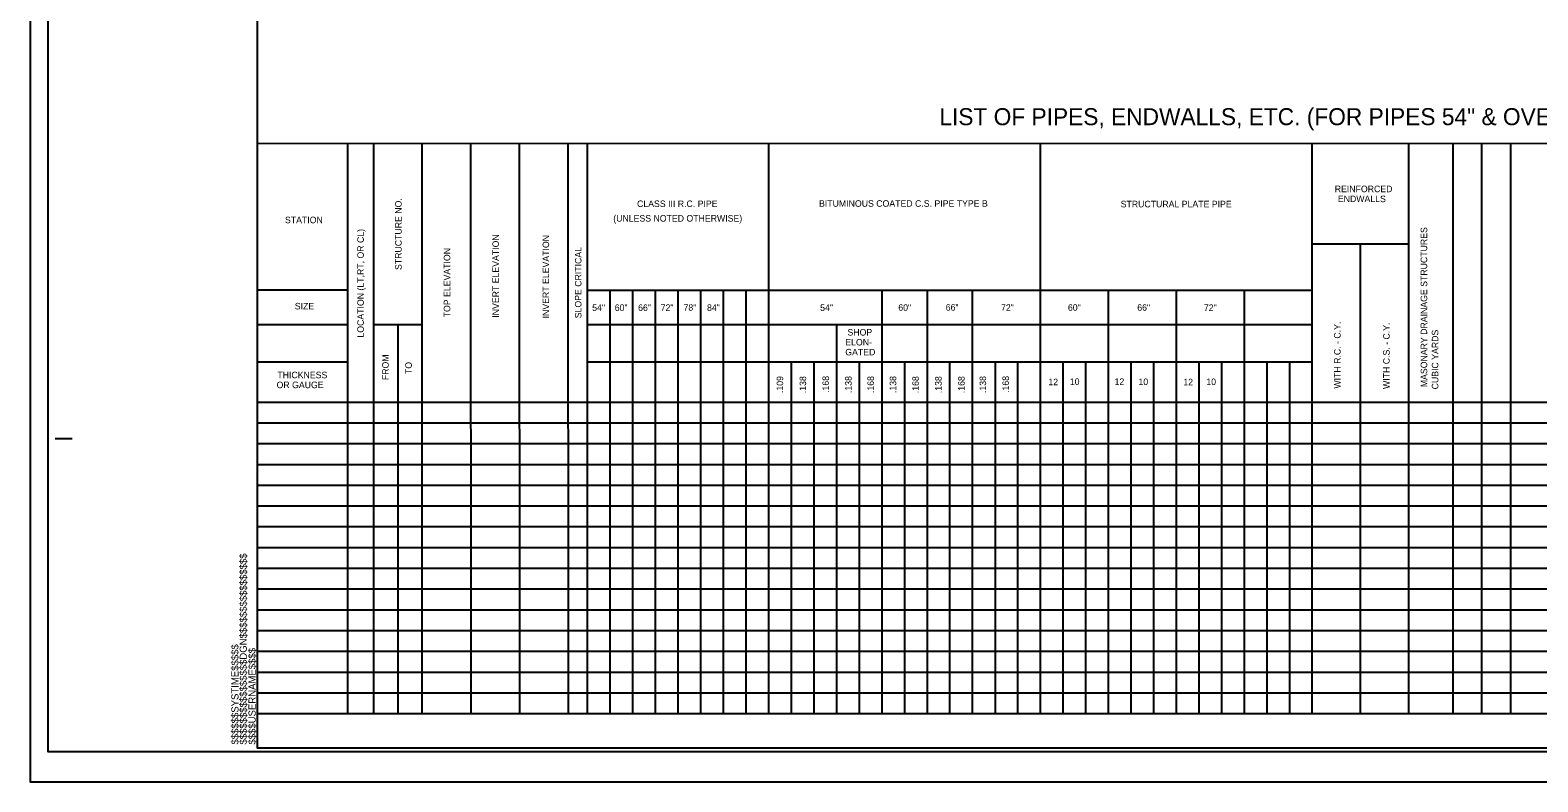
# Model space of a CAD drawing. Extents: x 2530399 to 2530799, y 189629 to 189994.
# Drawn here: x 2530630.3 to 2530741.2, y 189849.1 to 189904.4 of the extents above; entities that cross this region are included whole.
import ezdxf

# ---------------------------------------------------------------- set-up
doc = ezdxf.new("R2010")
doc.units = 0
for name, color, linetype in [('Sheet Plan CELL', 7, 'Continuous'), ('Typical Detail Pavement Repair CELL', 7, 'Continuous'), ('Typical Detail Wedge1 CELL', 7, 'Continuous'), ('Typical Pavement Slope Information CELL', 7, 'Continuous'), ('Typical Shoulder Slope CELL', 7, 'Continuous')]:
    doc.layers.add(name, color=color, linetype=linetype)

msp = doc.modelspace()

# ---------------------------------------------------------------- linework, layer by layer
at = {"layer": 'Sheet Plan CELL'}
for p, q in [((2530630.27, 189959.14), (2530630.27, 189849.14)), ((2530630.27, 189849.14), (2530798.67, 189849.14))]:
    msp.add_line(p, q, dxfattribs=at)
at = {"layer": 'Typical Detail Pavement Repair CELL'}
msp.add_lwpolyline([(2530798.22, 189956.89), (2530631.57, 189956.89), (2530631.57, 189851.38), (2530798.22, 189851.38)], close=True, dxfattribs=at)
at = {"layer": 'Typical Detail Wedge1 CELL'}
msp.add_lwpolyline([(2530798.67, 189959.14), (2530630.27, 189959.14), (2530630.27, 189849.14), (2530798.67, 189849.14)], close=True, dxfattribs=at)
at = {"layer": 'Typical Pavement Slope Information CELL'}
for p, q in [((2530632.12, 189874.39), (2530633.37, 189874.39)), ((2530646.97, 189851.64), (2530646.97, 189851.64))]:
    msp.add_line(p, q, dxfattribs=at)
msp.add_lwpolyline([(2530796.97, 189956.64), (2530646.97, 189956.64), (2530646.97, 189851.64), (2530796.97, 189851.64)], close=True, dxfattribs=at)
at = {"layer": 'Typical Shoulder Slope CELL'}
for p, q in [((2530796.96, 189896.09), (2530646.96, 189896.07)), ((2530653.65, 189854.14), (2530653.65, 189896.06)), ((2530655.56, 189854.14), (2530655.56, 189896.06)), ((2530659.12, 189854.14), (2530659.12, 189896.06)), ((2530662.71, 189854.14), (2530662.7, 189896.06)), ((2530666.29, 189854.14), (2530666.28, 189896.06)), ((2530669.87, 189854.14), (2530669.86, 189896.06)), ((2530671.28, 189854.14), (2530671.28, 189896.07)), ((2530684.62, 189854.14), (2530684.61, 189896.07)), ((2530704.61, 189854.14), (2530704.61, 189896.07)), ((2530724.6, 189854.14), (2530724.6, 189896.07)), ((2530731.71, 189854.14), (2530731.71, 189896.08)), ((2530734.93, 189896.07), (2530734.93, 189854.14)), ((2530737.07, 189854.14), (2530737.07, 189896.07)), ((2530739.21, 189854.14), (2530739.21, 189896.07)), ((2530731.71, 189888.68), (2530724.6, 189888.68)), ((2530728.15, 189854.14), (2530728.15, 189888.68)), ((2530653.65, 189885.29), (2530646.96, 189885.29)), ((2530669.87, 189885.28), (2530669.86, 189885.28)), ((2530671.28, 189885.29), (2530724.6, 189885.29)), ((2530672.95, 189854.14), (2530672.95, 189885.29)), ((2530674.62, 189854.14), (2530674.62, 189885.29)), ((2530676.28, 189854.14), (2530676.28, 189885.29)), ((2530677.95, 189854.14), (2530677.95, 189885.29)), ((2530679.61, 189854.14), (2530679.61, 189885.29)), ((2530681.28, 189854.14), (2530681.28, 189885.29)), ((2530682.95, 189854.14), (2530682.95, 189885.29)), ((2530692.95, 189854.14), (2530692.95, 189885.29)), ((2530696.28, 189854.14), (2530696.28, 189885.29)), ((2530699.61, 189854.14), (2530699.61, 189885.29)), ((2530709.6, 189854.14), (2530709.6, 189885.29)), ((2530714.61, 189854.14), (2530714.61, 189885.29)), ((2530719.6, 189854.14), (2530719.6, 189885.29)), ((2530653.65, 189882.75), (2530646.96, 189882.75)), ((2530659.12, 189882.75), (2530655.56, 189882.75)), ((2530657.34, 189854.14), (2530657.34, 189882.74)), ((2530666.28, 189882.74), (2530666.28, 189882.74)), ((2530669.87, 189882.74), (2530669.86, 189882.74)), ((2530724.6, 189882.75), (2530671.28, 189882.75)), ((2530689.61, 189854.14), (2530689.61, 189882.75)), ((2530653.65, 189880), (2530646.96, 189880)), ((2530724.6, 189880.01), (2530671.28, 189880)), ((2530686.28, 189854.14), (2530686.28, 189880)), ((2530687.94, 189854.14), (2530687.94, 189880)), ((2530691.28, 189854.14), (2530691.28, 189880)), ((2530694.61, 189854.14), (2530694.61, 189880)), ((2530697.94, 189854.14), (2530697.94, 189880)), ((2530701.28, 189854.14), (2530701.28, 189880)), ((2530702.94, 189854.14), (2530702.94, 189880)), ((2530706.27, 189854.14), (2530706.27, 189880)), ((2530707.94, 189854.14), (2530707.94, 189880)), ((2530711.27, 189854.14), (2530711.27, 189880)), ((2530712.94, 189854.14), (2530712.94, 189880.01)), ((2530716.27, 189854.14), (2530716.27, 189880.01)), ((2530717.94, 189854.14), (2530717.94, 189880.01)), ((2530721.27, 189854.14), (2530721.27, 189880.01)), ((2530722.94, 189854.14), (2530722.94, 189880.01)), ((2530796.96, 189877.04), (2530646.96, 189877.04)), ((2530796.96, 189875.51), (2530646.96, 189875.51)), ((2530796.96, 189873.99), (2530646.96, 189873.99)), ((2530796.96, 189872.46), (2530646.96, 189872.46)), ((2530796.96, 189870.93), (2530646.96, 189870.93)), ((2530796.96, 189869.41), (2530646.96, 189869.41)), ((2530796.96, 189867.88), (2530646.96, 189867.88)), ((2530796.96, 189866.35), (2530646.96, 189866.35)), ((2530796.96, 189864.83), (2530646.96, 189864.83)), ((2530796.96, 189863.3), (2530646.97, 189863.3)), ((2530796.96, 189861.77), (2530646.97, 189861.77)), ((2530796.96, 189860.24), (2530646.97, 189860.24)), ((2530796.96, 189858.72), (2530646.97, 189858.72)), ((2530796.96, 189857.19), (2530646.97, 189857.19)), ((2530796.96, 189855.66), (2530646.97, 189855.66)), ((2530796.96, 189854.14), (2530646.97, 189854.14))]:
    msp.add_line(p, q, dxfattribs=at)

# ---------------------------------------------------------------- texts
at = {"layer": 'Typical Pavement Slope Information CELL'}
for s, height, p in [('LIST OF PIPES, ENDWALLS, ETC. (FOR PIPES 54" & OVER)', 1.25, (2530697.16, 189897.43)), ('REINFORCED', 0.48, (2530726.25, 189892.5)), ('CLASS III R.C. PIPE', 0.48, (2530674.92, 189891.41)), ('BITUMINOUS COATED C.S. PIPE TYPE B', 0.48, (2530688.31, 189891.43)), ('STRUCTURAL PLATE PIPE', 0.48, (2530710.5, 189891.39)), (' ENDWALLS', 0.48, (2530726.3, 189891.77)), ('STATION', 0.48, (2530649.02, 189890.22)), ('(UNLESS NOTED OTHERWISE)', 0.48, (2530673.17, 189890.34)), ('SIZE', 0.48, (2530649.74, 189883.88)), ('54"', 0.48, (2530671.62, 189883.77)), ('60"', 0.48, (2530673.28, 189883.77)), ('66"', 0.48, (2530675, 189883.77)), ('72"', 0.48, (2530676.66, 189883.77)), ('78"', 0.48, (2530678.34, 189883.78)), ('84"', 0.48, (2530680.07, 189883.77)), ('54"', 0.48, (2530688.39, 189883.77)), ('60"', 0.48, (2530694.14, 189883.78)), ('66"', 0.48, (2530697.63, 189883.79)), ('72"', 0.48, (2530701.7, 189883.78)), ('60"', 0.48, (2530706.62, 189883.78)), ('66"', 0.48, (2530711.72, 189883.78)), ('72"', 0.48, (2530716.62, 189883.77)), ('SHOP', 0.48, (2530690.4, 189881.96)), ('GATED', 0.48, (2530690.24, 189880.5)), ('ELON-', 0.48, (2530690.24, 189881.23)), ('OR GAUGE', 0.48, (2530648.4, 189878.09)), ('THICKNESS', 0.48, (2530648.46, 189878.82)), ('12', 0.48, (2530705.18, 189878.31)), ('10', 0.48, (2530706.76, 189878.33)), ('12', 0.48, (2530710.05, 189878.33)), ('10', 0.48, (2530711.81, 189878.32)), ('12', 0.48, (2530715.11, 189878.3)), ('10', 0.48, (2530716.8, 189878.32))]:
    msp.add_text(s, height=height, dxfattribs=at).set_placement(p)
for s, height, p in [('STRUCTURE NO.', 0.48, (2530657.6, 189886.78)), ('LOCATION (LT,RT, OR CL)', 0.48, (2530654.82, 189881.81)), ('MASONARY DRAINAGE STRUCTURES ', 0.48, (2530733.05, 189878.16)), ('INVERT ELEVATION', 0.48, (2530664.76, 189883.27)), ('INVERT ELEVATION', 0.48, (2530668.45, 189883.22)), ('TOP ELEVATION', 0.48, (2530661.18, 189883.3)), ('SLOPE CRITICAL', 0.48, (2530670.83, 189883.23)), ('WITH R.C. - C.Y.', 0.48, (2530726.68, 189878.06)), ('WITH C.S. - C.Y.', 0.48, (2530730.29, 189878.03)), ('CUBIC YARDS', 0.48, (2530733.87, 189878)), ('FROM', 0.48, (2530656.65, 189878.68)), ('TO', 0.48, (2530658.35, 189879.13)), ('.109', 0.48, (2530685.67, 189877.73)), ('.138', 0.48, (2530687.36, 189877.72)), ('.168', 0.48, (2530689.04, 189877.74)), ('.138', 0.48, (2530690.71, 189877.73)), ('.168', 0.48, (2530692.35, 189877.73)), ('.138', 0.48, (2530693.99, 189877.73)), ('.168', 0.48, (2530695.65, 189877.72)), ('.138', 0.48, (2530697.33, 189877.72)), ('.168', 0.48, (2530699.02, 189877.72)), ('.138', 0.48, (2530700.6, 189877.73)), ('.168', 0.48, (2530702.28, 189877.74)), ('$$$$$$$$$$$$$$$$DGN$$$$$$$$$$$$$$$$', 0.525, (2530646.21, 189851.88)), ('$$$$$$SYSTIME$$$$$', 0.525, (2530645.6, 189851.88)), ('$$$$USERNAME$$$$', 0.525, (2530646.86, 189851.88))]:
    msp.add_text(s, height=height, rotation=90, dxfattribs=at).set_placement(p)

doc.saveas('drawing.dxf')
